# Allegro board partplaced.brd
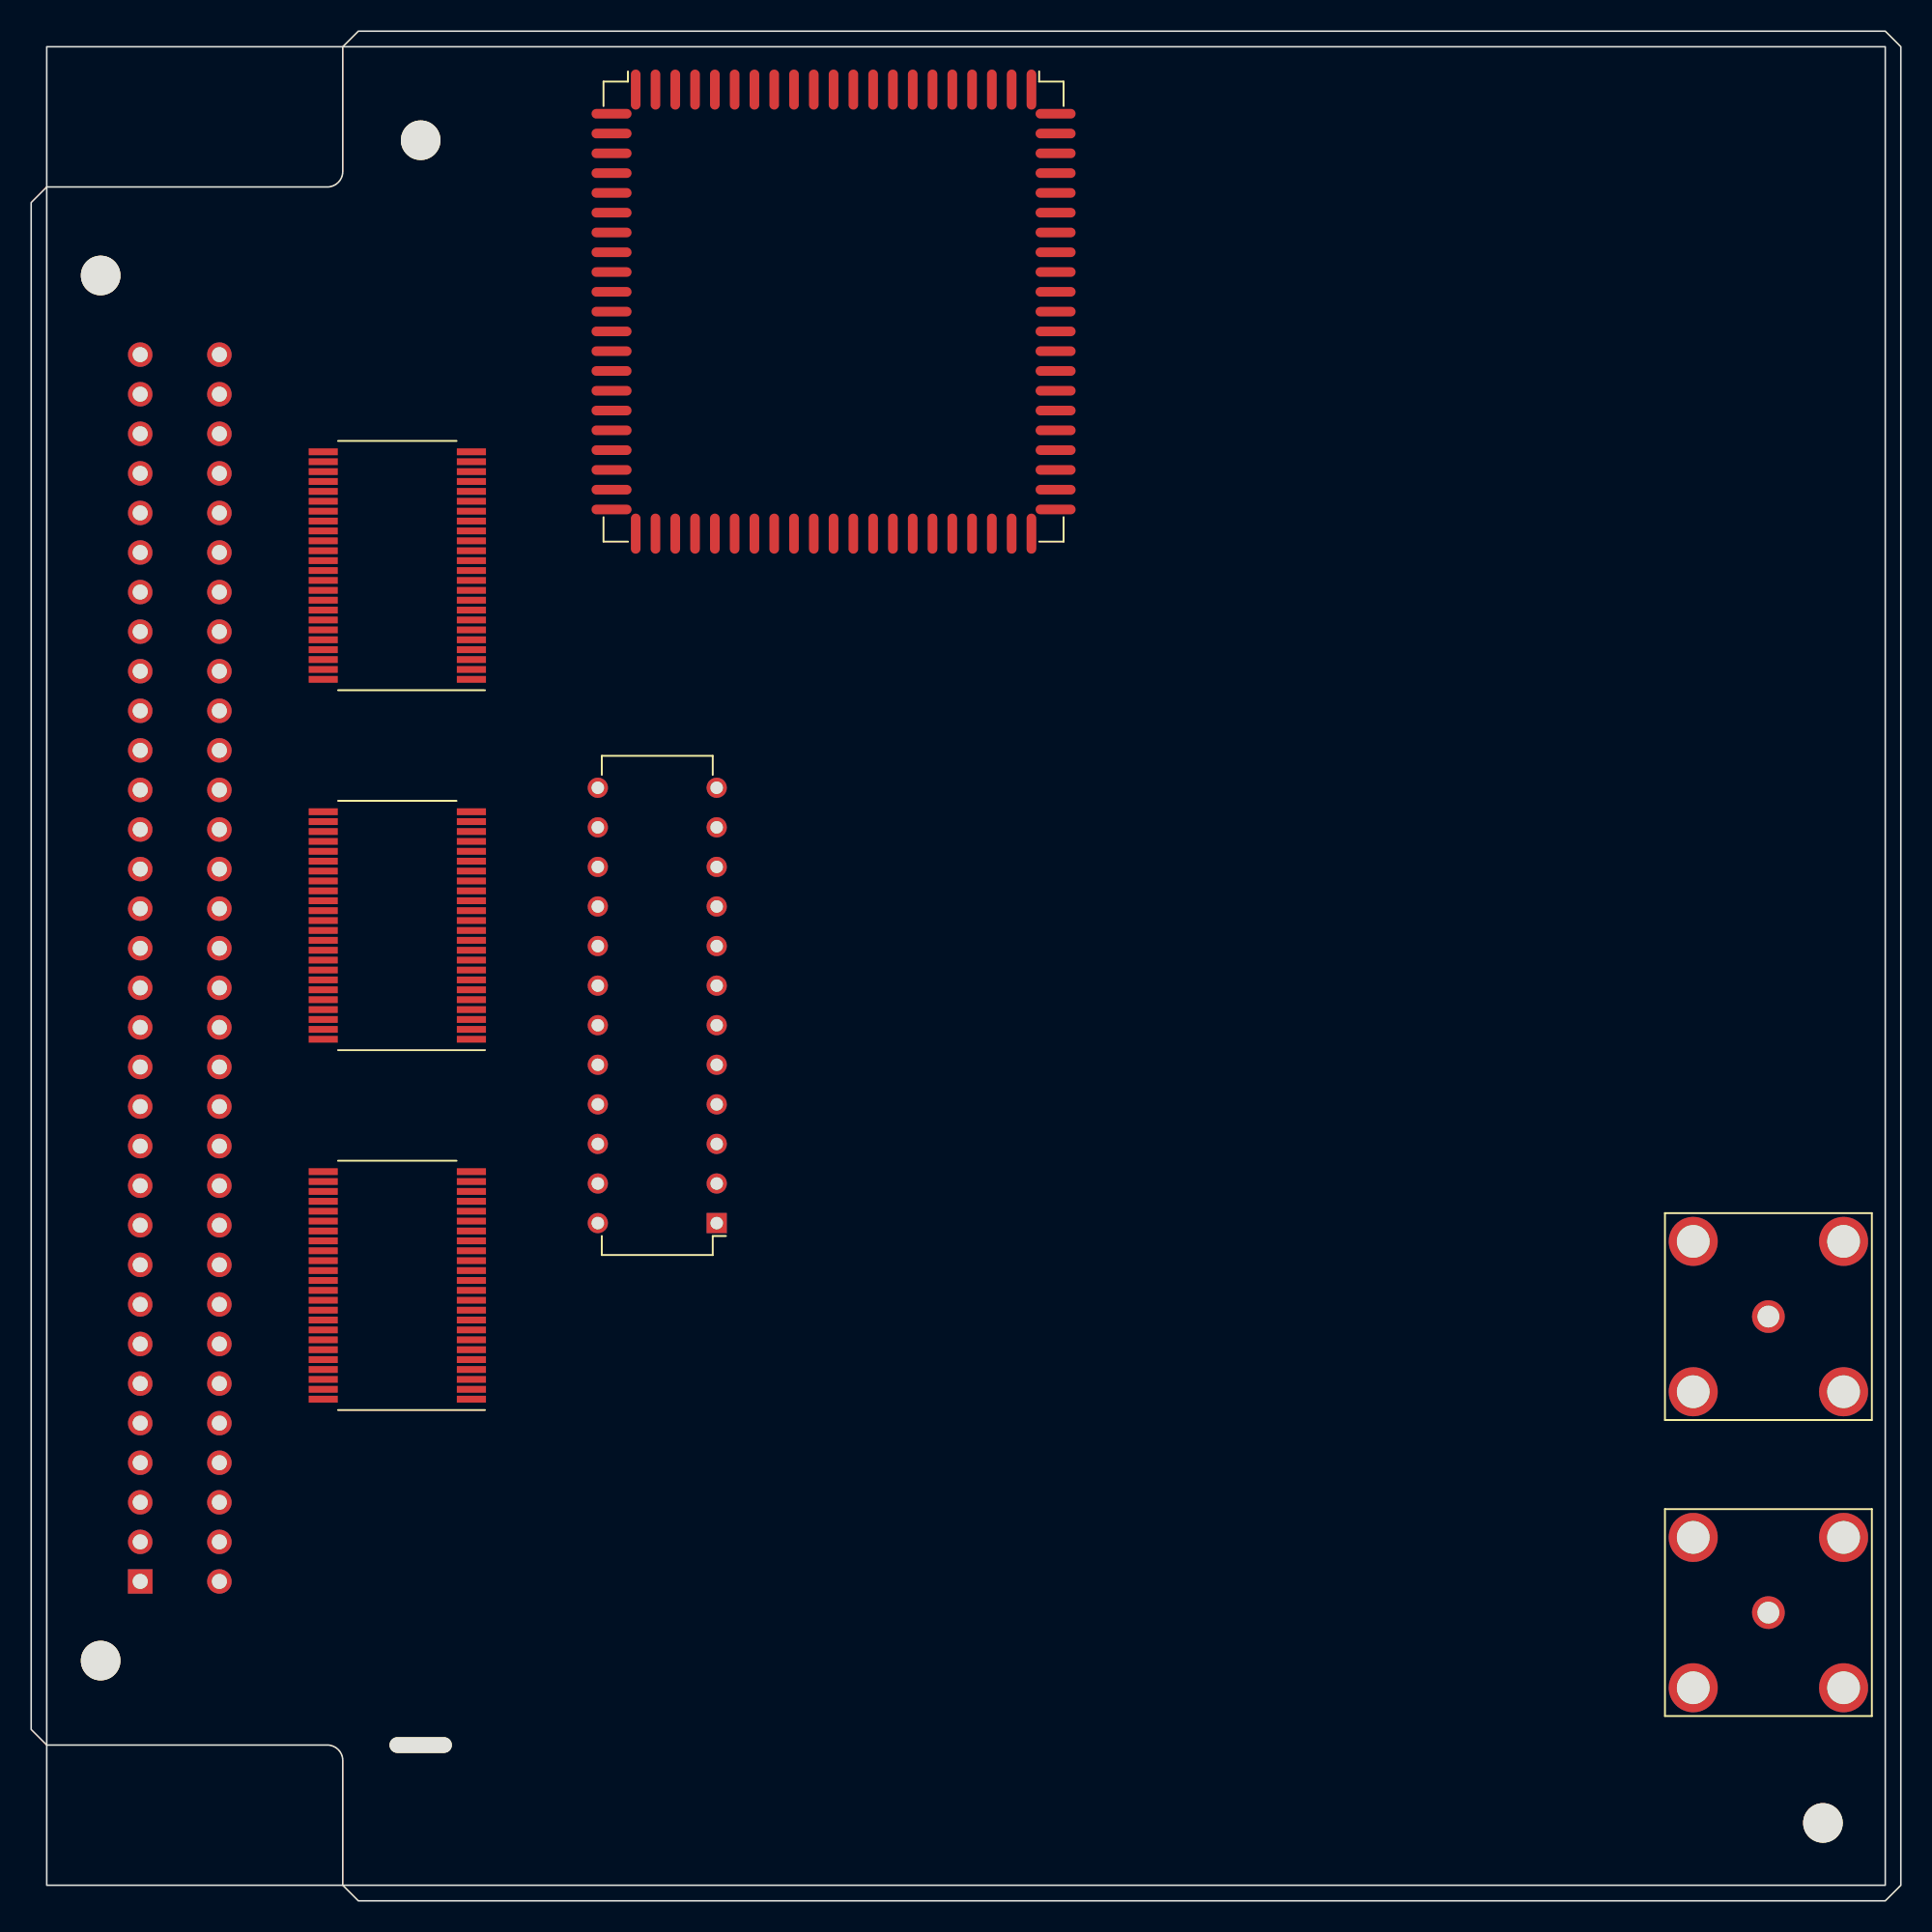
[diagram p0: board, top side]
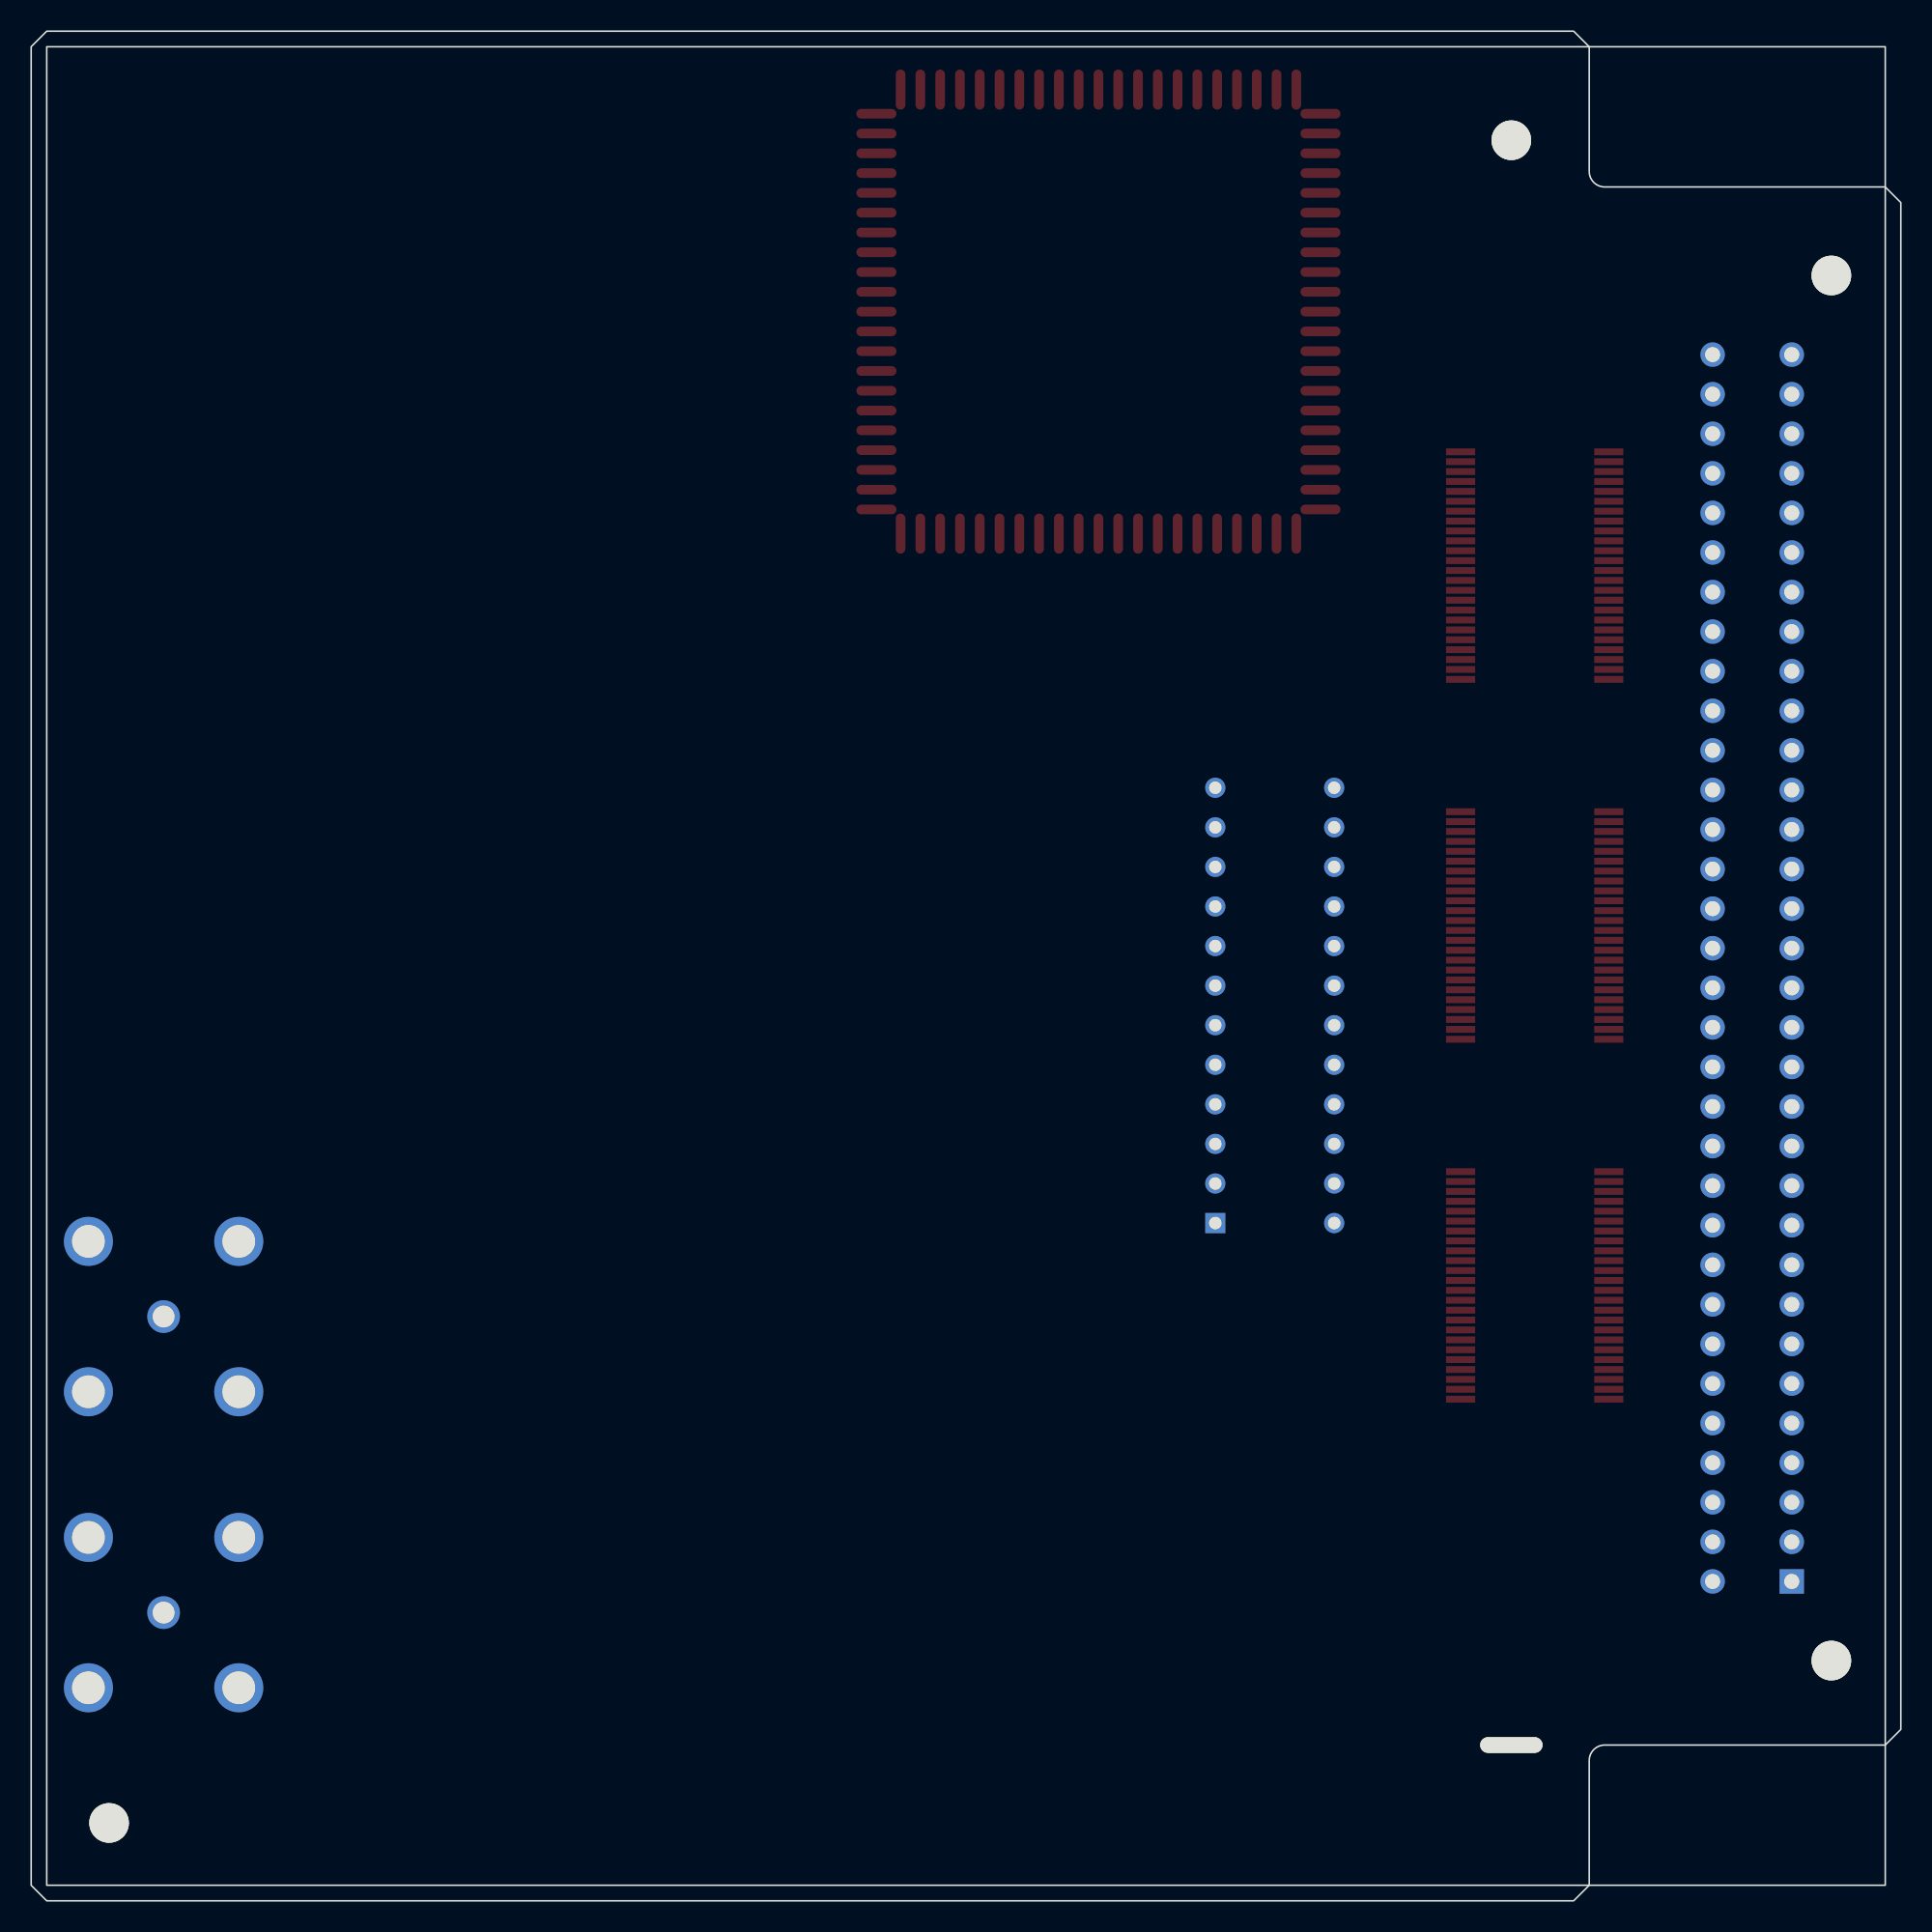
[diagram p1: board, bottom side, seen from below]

Outline 120 x 120 mm; copper layers: TOP, GND1, VCC1, VCC2, GND2, BOTTOM. Coordinates in mm from the lower left corner of the outline.
Outline path: rectangle 1,1 119,119

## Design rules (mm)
constraint set DEFAULT: min track width 0.15
net group SYNC: nets VCLKA VCLKC
net group MEMORY[0..28]: nets MEMORY.RA0 MEMORY.RA1 MEMORY.RA2 MEMORY.RA3 MEMORY.RA4 MEMORY.RA5 MEMORY.RA6 MEMORY.RA7 MEMORY.RA8 MEMORY.RA9 MEMORY.RA10 MEMORY.RA11 MEMORY.RA12 MEMORY.RA13 MEMORY.RA14 MEMORY.RA15 MEMORY.RCS0 MEMORY.RCS1 MEMORY.RCS2 MEMORY.RCS3 MEMORY.RD0 MEMORY.RD1 MEMORY.RD2 MEMORY.RD3 MEMORY.RD4 MEMORY.RD5 MEMORY.RD6 MEMORY.RD7 MEMORY.RWE
net group POWER: nets AGND GND_EARTH V12N V+12
net group VDNETS: nets VD0 VD1 VD2 VD3 VD4 VD5 VD6 VD7
nets with their own width: min track width 0.4; nets GND VCC

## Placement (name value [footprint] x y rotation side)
J1  CON64  [DIN64]  7 20.5 0 top
J2  BNC  [CONNEX_112659]  111.5 37.5 0 top
J3  BNC  [CONNEX_112659]  111.5 18.5 0 top
NOREF  -  []  25 10 90 top
NOREF#2  -  []  25.27 0 90 top
NOREF#3  -  [unnamed#2]  25 10 0 top
NOREF#4  -  []  20 4.47 0 top
NOREF#5  -  []  -71.52 -89.06 0 top
NOREF#6  -  []  119.43 119.57 0 top
NOREF#7  -  []  197.72 152.24 0 top
NOREF#8  -  []  25 10 0 top
NOREF#9  -  []  25 10 0 top
NOREF#10  -  []  25 10 90 top
NOREF#11  -  []  19.76 110.35 0 top
NOREF#12  -  []  25 10 90 top
NOREF#13  -  []  0 15.3 0 top
U1  FCT16245  [SOP63P1035X279-48N]  23.5 39.5 90 top
U2  20L10  [DIP763W46P254L3204H508Q24P]  44 43.5 90 top
U3  FCT16245  [SOP63P1035X279-48N]  23.5 62.6 90 top
U4  FCT16245  [SOP63P1035X279-48N]  23.5 85.7 90 top
U5  EPF8282A_LCC  [PLCC127P3022X3022X457-84N]  51.5 102 270 top

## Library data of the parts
J1 = CON64
J2 = BNC: room: CHAN1
J3 = BNC: room: CHAN2
U1 U3 U4 = FCT16245
U2 = 20L10: alternate symbols: (T:SOIC24;B:SOIC24_PE)
U5 = EPF8282A/LCC

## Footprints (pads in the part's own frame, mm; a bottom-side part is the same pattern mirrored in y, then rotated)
CONNEX_112659
  round 2.1 hole 1.4: 1(0,0)
  round 3.15 hole 2.1: 2(-4.825,4.825) 3(4.825,4.825) 4(4.825,-4.825) 5(-4.825,-4.825)
DIN64
  round 2.54 hole 2.794 unplated: (-2.54,83.82) (-2.54,-5.08)
  rect 1.575x1.575 hole 0.965: 1(0,0)
  round 1.575 hole 0.965: 2(0,2.54) 3(0,5.08) 4(0,7.62) 5(0,10.16) 6(0,12.7) 7(0,15.24) 8(0,17.78) 9(0,20.32) 10(0,22.86) 11(0,25.4) 12(0,27.94) 13(0,30.48) 14(0,33.02) 15(0,35.56) 16(0,38.1) 17(0,40.64) 18(0,43.18) 19(0,45.72) 20(0,48.26) 21(0,50.8) 22(0,53.34) 23(0,55.88) 24(0,58.42) 25(0,60.96) 26(0,63.5) 27(0,66.04) 28(0,68.58) 29(0,71.12) 30(0,73.66) 31(0,76.2) 32(0,78.74) 33(5.08,0) 34(5.08,2.54) 35(5.08,5.08) 36(5.08,7.62) 37(5.08,10.16) 38(5.08,12.7) 39(5.08,15.24) 40(5.08,17.78) 41(5.08,20.32) 42(5.08,22.86) 43(5.08,25.4) 44(5.08,27.94) 45(5.08,30.48) 46(5.08,33.02) 47(5.08,35.56) 48(5.08,38.1) 49(5.08,40.64) 50(5.08,43.18) 51(5.08,45.72) 52(5.08,48.26) 53(5.08,50.8) 54(5.08,53.34) 55(5.08,55.88) 56(5.08,58.42) 57(5.08,60.96) 58(5.08,63.5) 59(5.08,66.04) 60(5.08,68.58) 61(5.08,71.12) 62(5.08,73.66) 63(5.08,76.2) 64(5.08,78.74)
DIP763W46P254L3204H508Q24P
  rect 1.3x1.3 hole 0.8: 1(0,0)
  round 1.3 hole 0.8: 2(2.54,0) 3(5.08,0) 4(7.62,0) 5(10.16,0) 6(12.7,0) 7(15.24,0) 8(17.78,0) 9(20.32,0) 10(22.86,0) 11(25.4,0) 12(27.94,0) 13(27.94,7.63) 14(25.4,7.63) 15(22.86,7.63) 16(20.32,7.63) 17(17.78,7.63) 18(15.24,7.63) 19(12.7,7.63) 20(10.16,7.63) 21(7.62,7.63) 22(5.08,7.63) 23(2.54,7.63) 24(0,7.63)
PLCC127P3022X3022X457-84N
  oval 2.57x0.62 smd: 1(-14.25,0) 2(-14.25,-1.27) 3(-14.25,-2.54) 4(-14.25,-3.81) 5(-14.25,-5.08) 6(-14.25,-6.35) 7(-14.25,-7.62) 8(-14.25,-8.89) 9(-14.25,-10.16) 10(-14.25,-11.43) 11(-14.25,-12.7) 33(14.25,-12.7) 34(14.25,-11.43) 35(14.25,-10.16) 36(14.25,-8.89) 37(14.25,-7.62) 38(14.25,-6.35) 39(14.25,-5.08) 40(14.25,-3.81) 41(14.25,-2.54) 42(14.25,-1.27) 43(14.25,0) 44(14.25,1.27) 45(14.25,2.54) 46(14.25,3.81) 47(14.25,5.08) 48(14.25,6.35) 49(14.25,7.62) 50(14.25,8.89) 51(14.25,10.16) 52(14.25,11.43) 53(14.25,12.7) 75(-14.25,12.7) 76(-14.25,11.43) 77(-14.25,10.16) 78(-14.25,8.89) 79(-14.25,7.62) 80(-14.25,6.35) 81(-14.25,5.08) 82(-14.25,3.81) 83(-14.25,2.54) 84(-14.25,1.27)
  oval 0.62x2.57 smd: 12(-12.7,-14.25) 13(-11.43,-14.25) 14(-10.16,-14.25) 15(-8.89,-14.25) 16(-7.62,-14.25) 17(-6.35,-14.25) 18(-5.08,-14.25) 19(-3.81,-14.25) 20(-2.54,-14.25) 21(-1.27,-14.25) 22(0,-14.25) 23(1.27,-14.25) 24(2.54,-14.25) 25(3.81,-14.25) 26(5.08,-14.25) 27(6.35,-14.25) 28(7.62,-14.25) 29(8.89,-14.25) 30(10.16,-14.25) 31(11.43,-14.25) 32(12.7,-14.25) 54(12.7,14.25) 55(11.43,14.25) 56(10.16,14.25) 57(8.89,14.25) 58(7.62,14.25) 59(6.35,14.25) 60(5.08,14.25) 61(3.81,14.25) 62(2.54,14.25) 63(1.27,14.25) 64(0,14.25) 65(-1.27,14.25) 66(-2.54,14.25) 67(-3.81,14.25) 68(-5.08,14.25) 69(-6.35,14.25) 70(-7.62,14.25) 71(-8.89,14.25) 72(-10.16,14.25) 73(-11.43,14.25) 74(-12.7,14.25)
SOP63P1035X279-48N
  rect 0.44x1.87 smd: 1(-7.302,-4.755) 2(-6.668,-4.755) 3(-6.032,-4.755) 4(-5.398,-4.755) 5(-4.762,-4.755) 6(-4.128,-4.755) 7(-3.492,-4.755) 8(-2.858,-4.755) 9(-2.222,-4.755) 10(-1.588,-4.755) 11(-0.952,-4.755) 12(-0.318,-4.755) 13(0.318,-4.755) 14(0.952,-4.755) 15(1.588,-4.755) 16(2.222,-4.755) 17(2.858,-4.755) 18(3.492,-4.755) 19(4.128,-4.755) 20(4.762,-4.755) 21(5.398,-4.755) 22(6.032,-4.755) 23(6.668,-4.755) 24(7.302,-4.755) 25(7.302,4.755) 26(6.668,4.755) 27(6.032,4.755) 28(5.398,4.755) 29(4.762,4.755) 30(4.128,4.755) 31(3.492,4.755) 32(2.858,4.755) 33(2.222,4.755) 34(1.588,4.755) 35(0.952,4.755) 36(0.318,4.755) 37(-0.318,4.755) 38(-0.952,4.755) 39(-1.588,4.755) 40(-2.222,4.755) 41(-2.858,4.755) 42(-3.492,4.755) 43(-4.128,4.755) 44(-4.762,4.755) 45(-5.398,4.755) 46(-6.032,4.755) 47(-6.668,4.755) 48(-7.302,4.755)
unnamed#2
  round 2.54 hole 2.794 unplated: (0,103) (90,-5)
  oval 4x1 hole 5x1.5 unplated: (0,0)

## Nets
AGND: J1.34 J1.35 J1.36
GND: J1.1 J1.2 J1.3 J1.33 U1.4 U1.10 U1.15 U1.21 U1.24 U1.25(G\) U1.28 U1.34 U1.39 U1.45 U2.11 U2.12 U2.13 U3.4 U3.10 U3.15 U3.21 U3.24 U3.25(G\) U3.28 U3.34 U3.39 U3.45 U4.4 U4.10 U4.15 U4.21 U4.24 U4.25(G\) U4.28 U4.34 U4.39 U4.45 U5.5 U5.26 U5.47 U5.53 U5.68 U5.74 U5.75
GND_EARTH: J2.2 J2.3 J2.4 J2.5(GND5) J3.2 J3.3 J3.4 J3.5(GND5)
V12N: J1.31 J1.32
VCC: J1.29 J1.30 J1.62 U1.7 U1.18 U1.31 U1.42 U2.24(VCC) U3.7 U3.18 U3.31 U3.42 U4.7 U4.18 U4.31 U4.42 U5.17 U5.38 U5.59 U5.80
A0: J1.54 U4.47
A1: J1.55 U4.46
A2: J1.56 U4.44
A3: J1.57 U4.43
A4: J1.58 U4.41
A5: J1.59 U4.40
A6: J1.60 U4.38
A7: J1.61 U4.37
A8: J1.13 U3.47
A9: J1.14 U3.46
A10: J1.15 U3.44
A11: J1.16 U3.43
A12: J1.17 U3.41
A13: J1.18 U3.40
A14: J1.19 U3.38
A15: J1.20 U3.37
A16: J1.37 U1.47
A17: J1.38 U1.46
A18: J1.39 U1.44 U2.6
A19: J1.40 U1.43 U2.5
A20: J1.41 U1.41 U2.4
A21: J1.42 U1.40 U2.3
A22: J1.43 U1.38 U2.2
A23: J1.44 U1.37 U2.1
AEN: J1.47 U2.8
BA0: U1.13 U3.13 U4.13 U5.6
BA1: U1.14 U3.14 U4.14 U5.7
BA2: U1.16 U3.16 U4.16 U5.8
BA3: U1.17 U3.17 U4.17 U5.9
BA4: U1.19 U3.19 U4.19
BA5: U1.20 U3.20 U4.20
BA6: U1.22 U3.22 U4.22
BA7: U1.23 U3.23 U4.23
BD0: U4.12 U5.25
BD1: U4.11 U5.24
BD2: U4.9 U5.23
BD3: U4.8 U5.22
BD4: U4.6 U5.21
BD5: U4.5 U5.20
BD6: U4.3 U5.19
BD7: U4.2 U5.18
BD8: U1.12 U3.2
BD9: U1.11 U3.3
BD10: U1.9 U3.5
BD11: U1.8 U3.6
BD12: U1.6 U3.8
BD13: U1.5 U3.9
BD14: U1.3 U3.11
BD15: U1.2 U3.12
BNC2: J2.1
BNC3: J3.1
BRD: U2.16 U5.73
BRESET: U2.15 U5.12
BWR: U2.17 U5.54
D0: J1.28 U3.26 U4.26
D1: J1.27 U3.27 U4.27
D2: J1.26 U3.29 U4.29
D3: J1.25 U3.30 U4.30
D4: J1.24 U3.32 U4.32
D5: J1.23 U3.33 U4.33
D6: J1.22 U3.35 U4.35
D7: J1.21 U3.36 U4.36
D8: J1.4 U1.36
D9: J1.5 U1.35
D10: J1.6 U1.33
D11: J1.7 U1.32
D12: J1.8 U1.30
D13: J1.9 U1.29
D14: J1.10 U1.27
D15: J1.11 U1.26
DATA: U5.14
DCLK: U5.10
DDIR: U1.48 U2.20 U3.48 U4.48
DEN: U1.1 U2.21 U4.1
DHEN: U2.22 U3.1
FPGA: U2.18 U5.30
GAIN: U5.28
HS: U2.19 U5.29
MCLK: J1.52 U5.31
MEMORY.RA0: U5.79
MEMORY.RA1: U5.78
MEMORY.RA2: U5.77
MEMORY.RA3: U5.76
MEMORY.RA4: U5.71
MEMORY.RA5: U5.70
MEMORY.RA6: U5.69
MEMORY.RA7: U5.67
MEMORY.RA8: U5.66
MEMORY.RA9: U5.65
MEMORY.RA10: U5.64
MEMORY.RA11: U5.63
MEMORY.RA12: U5.62
MEMORY.RA13: U5.61
MEMORY.RA14: U5.60
MEMORY.RA15: U5.58
MEMORY.RCS0: U5.51
MEMORY.RCS1: U5.50
MEMORY.RCS2: U5.49
MEMORY.RCS3: U5.48
MEMORY.RD0: U5.81
MEMORY.RD1: U5.82
MEMORY.RD2: U5.83
MEMORY.RD3: U5.84
MEMORY.RD4: U5.1
MEMORY.RD5: U5.2
MEMORY.RD6: U5.3
MEMORY.RD7: U5.4
MEMORY.RWE: U5.56
MRD: J1.46 U2.9
MWR: J1.45 U2.10
NCS: U5.11
OE: U5.32
RDY: J1.50 U2.23
RESET: J1.53 U5.15
SEL: U2.14 U5.13
V+12: J1.63 J1.64
VCLKA: U5.34
VD0: U5.39
VD1: U5.40
VD2: U5.41
VD3: U5.42
VD4: U5.43
VD5: U5.44
VD6: U5.45
VD7: U5.46(VD7)
WAIT: J1.51 U5.33
WSTAT: U5.57
N409523: U5.37

Pads without a net: J1 12 48 49; U2 7; U5 16 27 35 36 52 55 72
